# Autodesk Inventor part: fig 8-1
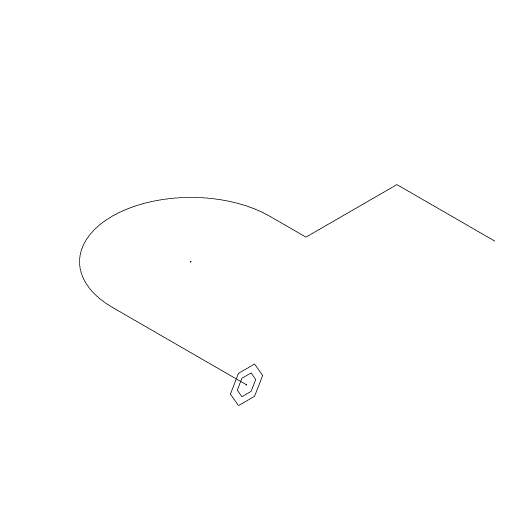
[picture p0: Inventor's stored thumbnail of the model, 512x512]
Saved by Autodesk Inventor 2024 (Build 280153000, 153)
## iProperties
Created: 2004-05
Part Number: fig 8-1
Document SubType Name: Modeling
Designer: CADCIM Technologies
Manufacturer: Standard
Standards Organization: Custom
Density: 1 g/cm^3
Material: Generic
Appearance: Default
Author: CADCIM Technologies
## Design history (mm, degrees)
sketch "Sketch1"
  geometry: L1 (-42.583, 3.219)-(-90.066, 3.219); L2 (-90.066, 58.92)-(-77.282, 58.92); L3 (-77.282, 58.92)-(-77.282, 91.063); L4 (-77.282, 91.063)-(-42.583, 91.063); A1 r 27.851 centre (-90.066, 31.07) between (-90.066, 58.92) and (-90.066, 3.219)
  constraints: 8 end point, 2 parallel, 2 point on circle, 2 tangent, 1 centre point, 1 perpendicular
workplane "Work Plane2"
sketch "Sketch2"
  geometry: L1 (-5.697, 0)-(-2.849, 4.934); L2 (-2.849, 4.934)-(2.849, 4.934); L3 (2.849, 4.934)-(5.697, 0); L4 (5.697, 0)-(2.849, -4.934); L5 (2.849, -4.934)-(-2.849, -4.934); L6 (-2.849, -4.934)-(-5.697, 0); L7 (-3.256, 0)-(-1.628, 2.819); L8 (-1.628, 2.819)-(1.628, 2.819); L9 (1.628, 2.819)-(3.256, 0); L10 (3.256, 0)-(1.628, -2.819); L11 (1.628, -2.819)-(-1.628, -2.819); L12 (-1.628, -2.819)-(-3.256, 0); 2 further points
  constraints: 24 end point, 1 coincident, 22 other
